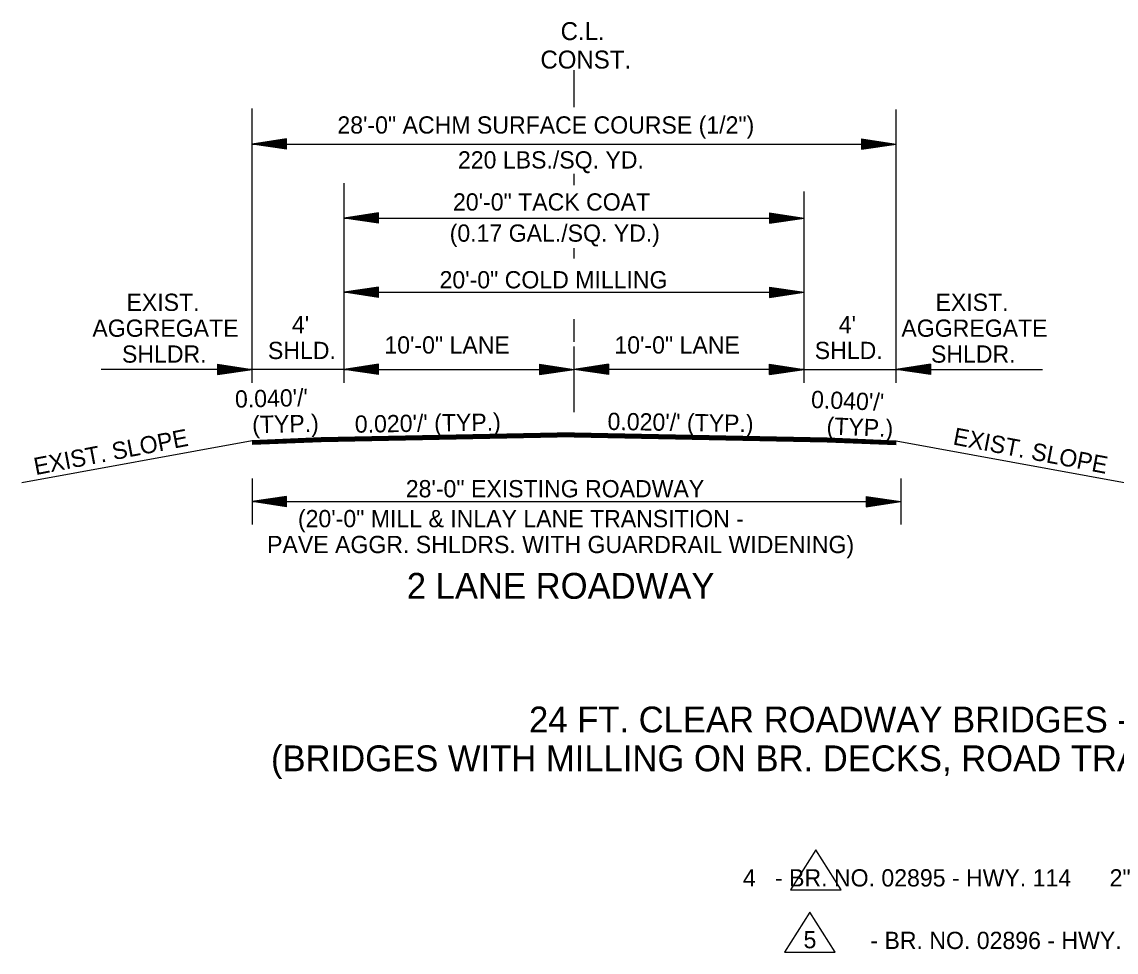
# Model space of a CAD drawing. Extents: x 544259 to 1930787, y -1961343 to 596640.
# Drawn here: x 544331.2 to 544806.9, y -1956857.9 to -1956453.5 of the extents above; entities that cross this region are included whole.
import ezdxf

# ---------------------------------------------------------------- set-up
doc = ezdxf.new("R2010")
doc.units = 0
doc.layers.add('R_Border', color=7, linetype='Continuous')
doc.layers.add('R_Draft', color=7, linetype='Continuous')

msp = doc.modelspace()

# ---------------------------------------------------------------- linework, layer by layer
at = {"layer": 'R_Border'}
for p, q in [((544461.23, -1956634.36), (544431.23, -1956635.56)), ((544461.23, -1956634.66), (544431.23, -1956635.86)), ((544681.23, -1956634.36), (544711.23, -1956635.56)), ((544681.23, -1956634.66), (544711.23, -1956635.86)), ((544461.23, -1956634.96), (544431.23, -1956636.16)), ((544461.23, -1956635.26), (544431.23, -1956636.46)), ((544461.23, -1956635.56), (544431.23, -1956636.76)), ((544461.23, -1956635.86), (544431.23, -1956637.06)), ((544461.23, -1956636.03), (544431.23, -1956637.23)), ((544681.23, -1956634.96), (544711.23, -1956636.16)), ((544681.23, -1956635.26), (544711.23, -1956636.46)), ((544681.23, -1956635.56), (544711.23, -1956636.76)), ((544681.23, -1956635.86), (544711.23, -1956637.06)), ((544681.23, -1956636.03), (544711.23, -1956637.23)), ((544676.31, -1956813.47), (544665.27, -1956830.77)), ((544687.35, -1956830.77), (544676.31, -1956813.47)), ((544665.27, -1956830.77), (544687.35, -1956830.77)), ((544673.76, -1956840.6), (544662.71, -1956857.9)), ((544684.8, -1956857.9), (544673.76, -1956840.6)), ((544662.71, -1956857.9), (544684.8, -1956857.9))]:
    msp.add_line(p, q, dxfattribs=at)
at = {"layer": 'R_Draft'}
for p, q in [((544571.23, -1956490.58), (544571.23, -1956474.51)), ((544431.23, -1956610.43), (544431.23, -1956491.09)), ((544711.23, -1956610.43), (544711.23, -1956491.65)), ((544446.23, -1956504.38), (544431.23, -1956506.63)), ((544446.23, -1956504.76), (544433.73, -1956506.63)), ((544446.23, -1956505.14), (544436.31, -1956506.63)), ((544446.23, -1956505.51), (544438.81, -1956506.63)), ((544446.23, -1956505.9), (544441.35, -1956506.63)), ((544446.23, -1956508.88), (544446.23, -1956504.38)), ((544696.23, -1956504.38), (544711.23, -1956506.63)), ((544696.23, -1956504.38), (544696.23, -1956508.88)), ((544696.23, -1956504.76), (544708.72, -1956506.63)), ((544696.23, -1956505.14), (544706.14, -1956506.63)), ((544696.23, -1956505.51), (544703.65, -1956506.63)), ((544696.23, -1956505.9), (544701.1, -1956506.63)), ((544431.23, -1956506.63), (544711.23, -1956506.63)), ((544446.23, -1956508.88), (544431.23, -1956506.63)), ((544446.23, -1956508.51), (544433.73, -1956506.63)), ((544446.23, -1956508.12), (544436.31, -1956506.63)), ((544446.23, -1956507.75), (544438.81, -1956506.63)), ((544446.23, -1956507.36), (544441.35, -1956506.63)), ((544446.23, -1956506.28), (544443.86, -1956506.63)), ((544446.23, -1956506.98), (544443.86, -1956506.63)), ((544696.23, -1956506.28), (544698.6, -1956506.63)), ((544696.23, -1956508.88), (544711.23, -1956506.63)), ((544696.23, -1956507.37), (544701.1, -1956506.63)), ((544696.23, -1956508.12), (544706.14, -1956506.63)), ((544696.23, -1956508.51), (544708.72, -1956506.63)), ((544696.23, -1956507.75), (544703.65, -1956506.63)), ((544696.23, -1956506.98), (544698.6, -1956506.63)), ((544571.23, -1956524.52), (544571.23, -1956519.49)), ((544471.23, -1956610.43), (544471.23, -1956523.61)), ((544671.23, -1956610.43), (544671.23, -1956527.27)), ((544486.23, -1956536.53), (544471.23, -1956538.78)), ((544471.23, -1956538.78), (544671.23, -1956538.78)), ((544486.23, -1956541.03), (544471.23, -1956538.78)), ((544486.23, -1956536.9), (544473.73, -1956538.78)), ((544486.23, -1956540.65), (544473.73, -1956538.78)), ((544486.23, -1956537.29), (544476.31, -1956538.78)), ((544486.23, -1956540.27), (544476.31, -1956538.78)), ((544486.23, -1956537.66), (544478.81, -1956538.78)), ((544486.23, -1956539.9), (544478.81, -1956538.78)), ((544486.23, -1956538.04), (544481.35, -1956538.78)), ((544486.23, -1956539.51), (544481.35, -1956538.78)), ((544486.23, -1956538.43), (544483.86, -1956538.78)), ((544486.23, -1956539.13), (544483.86, -1956538.78)), ((544486.23, -1956541.03), (544486.23, -1956536.53)), ((544656.23, -1956536.53), (544671.23, -1956538.78)), ((544656.23, -1956536.53), (544656.23, -1956541.03)), ((544656.23, -1956536.9), (544668.72, -1956538.78)), ((544656.23, -1956537.29), (544666.14, -1956538.78)), ((544656.23, -1956537.66), (544663.65, -1956538.78)), ((544656.23, -1956538.05), (544661.1, -1956538.78)), ((544656.23, -1956538.43), (544658.6, -1956538.78)), ((544656.23, -1956541.03), (544671.23, -1956538.78)), ((544656.23, -1956539.51), (544661.1, -1956538.78)), ((544656.23, -1956540.27), (544666.14, -1956538.78)), ((544656.23, -1956540.65), (544668.72, -1956538.78)), ((544656.23, -1956539.9), (544663.65, -1956538.78)), ((544656.23, -1956539.13), (544658.6, -1956538.78)), ((544571.23, -1956556.37), (544571.23, -1956551.91)), ((544486.23, -1956568.77), (544471.23, -1956571.02)), ((544471.23, -1956571.02), (544671.23, -1956571.02)), ((544486.23, -1956573.27), (544471.23, -1956571.02)), ((544486.23, -1956569.14), (544473.73, -1956571.02)), ((544486.23, -1956572.89), (544473.73, -1956571.02)), ((544486.23, -1956569.53), (544476.31, -1956571.02)), ((544486.23, -1956572.51), (544476.31, -1956571.02)), ((544486.23, -1956569.9), (544478.81, -1956571.02)), ((544486.23, -1956572.14), (544478.81, -1956571.02)), ((544486.23, -1956570.28), (544481.35, -1956571.02)), ((544486.23, -1956571.75), (544481.35, -1956571.02)), ((544486.23, -1956570.67), (544483.86, -1956571.02)), ((544486.23, -1956571.37), (544483.86, -1956571.02)), ((544486.23, -1956573.27), (544486.23, -1956568.77)), ((544656.23, -1956568.77), (544671.23, -1956571.02)), ((544656.23, -1956568.77), (544656.23, -1956573.27)), ((544656.23, -1956569.14), (544668.72, -1956571.02)), ((544656.23, -1956569.53), (544666.14, -1956571.02)), ((544656.23, -1956569.9), (544663.65, -1956571.02)), ((544656.23, -1956570.29), (544661.1, -1956571.02)), ((544656.23, -1956570.67), (544658.6, -1956571.02)), ((544656.23, -1956573.27), (544671.23, -1956571.02)), ((544656.23, -1956571.75), (544661.1, -1956571.02)), ((544656.23, -1956572.51), (544666.14, -1956571.02)), ((544656.23, -1956572.89), (544668.72, -1956571.02)), ((544656.23, -1956572.14), (544663.65, -1956571.02)), ((544656.23, -1956571.37), (544658.6, -1956571.02)), ((544571.23, -1956584.55), (544571.23, -1956582.67)), ((544571.23, -1956592.54), (544571.23, -1956584.55)), ((544571.23, -1956623.21), (544571.23, -1956594.66)), ((544471.23, -1956604.56), (544365.65, -1956604.56)), ((544416.23, -1956602.31), (544431.23, -1956604.56)), ((544416.23, -1956602.31), (544416.23, -1956606.81)), ((544416.23, -1956602.68), (544428.72, -1956604.56)), ((544416.23, -1956603.06), (544426.14, -1956604.56)), ((544416.23, -1956603.44), (544423.65, -1956604.56)), ((544416.23, -1956603.83), (544421.1, -1956604.56)), ((544416.23, -1956604.2), (544418.6, -1956604.56)), ((544416.23, -1956606.81), (544431.23, -1956604.56)), ((544416.23, -1956605.29), (544421.1, -1956604.56)), ((544416.23, -1956606.05), (544426.14, -1956604.56)), ((544416.23, -1956606.43), (544428.72, -1956604.56)), ((544416.23, -1956605.67), (544423.65, -1956604.56)), ((544416.23, -1956604.91), (544418.6, -1956604.56)), ((544486.23, -1956602.31), (544471.23, -1956604.56)), ((544486.23, -1956606.81), (544471.23, -1956604.56)), ((544471.23, -1956604.56), (544571.23, -1956604.56)), ((544486.23, -1956602.68), (544473.73, -1956604.56)), ((544486.23, -1956606.43), (544473.73, -1956604.56)), ((544486.23, -1956603.06), (544476.31, -1956604.56)), ((544486.23, -1956606.05), (544476.31, -1956604.56)), ((544486.23, -1956603.44), (544478.81, -1956604.56)), ((544486.23, -1956605.67), (544478.81, -1956604.56)), ((544486.23, -1956603.82), (544481.35, -1956604.56)), ((544486.23, -1956605.28), (544481.35, -1956604.56)), ((544486.23, -1956604.2), (544483.86, -1956604.56)), ((544486.23, -1956604.91), (544483.86, -1956604.56)), ((544486.23, -1956606.81), (544486.23, -1956602.31)), ((544556.23, -1956602.31), (544571.23, -1956604.56)), ((544556.23, -1956602.31), (544556.23, -1956606.81)), ((544556.23, -1956602.68), (544568.72, -1956604.56)), ((544556.23, -1956603.06), (544566.14, -1956604.56)), ((544556.23, -1956603.44), (544563.65, -1956604.56)), ((544556.23, -1956603.83), (544561.1, -1956604.56)), ((544556.23, -1956604.2), (544558.6, -1956604.56)), ((544556.23, -1956606.81), (544571.23, -1956604.56)), ((544556.23, -1956605.29), (544561.1, -1956604.56)), ((544556.23, -1956606.05), (544566.14, -1956604.56)), ((544556.23, -1956606.43), (544568.72, -1956604.56)), ((544556.23, -1956605.67), (544563.65, -1956604.56)), ((544556.23, -1956604.91), (544558.6, -1956604.56)), ((544586.23, -1956602.31), (544571.23, -1956604.56)), ((544671.23, -1956604.56), (544571.23, -1956604.56)), ((544586.23, -1956606.81), (544571.23, -1956604.56)), ((544586.23, -1956602.68), (544573.73, -1956604.56)), ((544586.23, -1956606.43), (544573.73, -1956604.56)), ((544586.23, -1956603.06), (544576.31, -1956604.56)), ((544586.23, -1956606.05), (544576.31, -1956604.56)), ((544586.23, -1956603.44), (544578.81, -1956604.56)), ((544586.23, -1956605.67), (544578.81, -1956604.56)), ((544586.23, -1956603.83), (544581.35, -1956604.56)), ((544586.23, -1956605.29), (544581.35, -1956604.56)), ((544586.23, -1956604.2), (544583.86, -1956604.56)), ((544586.23, -1956604.91), (544583.86, -1956604.56)), ((544586.23, -1956602.31), (544586.23, -1956606.81)), ((544656.23, -1956602.31), (544671.23, -1956604.56)), ((544656.23, -1956606.81), (544656.23, -1956602.31)), ((544656.23, -1956602.68), (544668.72, -1956604.56)), ((544656.23, -1956603.06), (544666.14, -1956604.56)), ((544656.23, -1956603.44), (544663.65, -1956604.56)), ((544656.23, -1956603.82), (544661.1, -1956604.56)), ((544656.23, -1956604.2), (544658.6, -1956604.56)), ((544656.23, -1956606.81), (544671.23, -1956604.56)), ((544656.23, -1956605.28), (544661.1, -1956604.56)), ((544656.23, -1956606.05), (544666.14, -1956604.56)), ((544656.23, -1956606.43), (544668.72, -1956604.56)), ((544656.23, -1956605.67), (544663.65, -1956604.56)), ((544656.23, -1956604.91), (544658.6, -1956604.56)), ((544671.35, -1956604.56), (544774.91, -1956604.56)), ((544726.23, -1956602.31), (544711.23, -1956604.56)), ((544726.23, -1956606.81), (544711.23, -1956604.56)), ((544726.23, -1956602.68), (544713.73, -1956604.56)), ((544726.23, -1956606.43), (544713.73, -1956604.56)), ((544726.23, -1956603.06), (544716.31, -1956604.56)), ((544726.23, -1956606.05), (544716.31, -1956604.56)), ((544726.23, -1956603.44), (544718.81, -1956604.56)), ((544726.23, -1956605.67), (544718.81, -1956604.56)), ((544726.23, -1956603.83), (544721.35, -1956604.56)), ((544726.23, -1956605.29), (544721.35, -1956604.56)), ((544726.23, -1956604.2), (544723.86, -1956604.56)), ((544726.23, -1956604.91), (544723.86, -1956604.56)), ((544726.23, -1956602.31), (544726.23, -1956606.81)), ((544571.23, -1956632.16), (544461.23, -1956634.36)), ((544571.22, -1956632.46), (544461.23, -1956634.66)), ((544571.23, -1956632.76), (544461.23, -1956634.96)), ((544571.25, -1956633.06), (544461.23, -1956635.26)), ((544571.25, -1956633.36), (544461.23, -1956635.56)), ((544571.26, -1956633.66), (544461.23, -1956635.86)), ((544571.26, -1956633.83), (544461.23, -1956636.03)), ((544571.2, -1956633.36), (544681.23, -1956635.56)), ((544571.2, -1956633.66), (544681.23, -1956635.86)), ((544571.2, -1956633.83), (544681.23, -1956636.03)), ((544571.21, -1956633.06), (544681.23, -1956635.26)), ((544571.22, -1956632.46), (544681.23, -1956634.66)), ((544571.22, -1956632.76), (544681.23, -1956634.96)), ((544571.23, -1956632.16), (544681.23, -1956634.36)), ((544431.23, -1956635.56), (544331.16, -1956653.94)), ((544711.23, -1956635.56), (544811.3, -1956653.94)), ((544431.23, -1956652.02), (544431.23, -1956672.02)), ((544713.23, -1956652.02), (544713.23, -1956672.02)), ((544446.23, -1956659.77), (544431.23, -1956662.02)), ((544431.23, -1956662.02), (544711.23, -1956662.02)), ((544446.23, -1956664.27), (544431.23, -1956662.02)), ((544446.23, -1956660.14), (544433.73, -1956662.02)), ((544446.23, -1956663.89), (544433.73, -1956662.02)), ((544446.23, -1956660.53), (544436.31, -1956662.02)), ((544446.23, -1956663.51), (544436.31, -1956662.02)), ((544446.23, -1956660.9), (544438.81, -1956662.02)), ((544446.23, -1956663.14), (544438.81, -1956662.02)), ((544446.23, -1956661.28), (544441.35, -1956662.02)), ((544446.23, -1956662.75), (544441.35, -1956662.02)), ((544446.23, -1956661.67), (544443.86, -1956662.02)), ((544446.23, -1956662.37), (544443.86, -1956662.02)), ((544446.23, -1956664.27), (544446.23, -1956659.77)), ((544698.23, -1956659.77), (544713.23, -1956662.02)), ((544698.23, -1956659.77), (544698.23, -1956664.27)), ((544698.23, -1956660.14), (544710.72, -1956662.02)), ((544698.23, -1956660.53), (544708.14, -1956662.02)), ((544698.23, -1956660.9), (544705.65, -1956662.02)), ((544698.23, -1956661.29), (544703.1, -1956662.02)), ((544698.23, -1956661.67), (544700.6, -1956662.02)), ((544698.23, -1956664.27), (544713.23, -1956662.02)), ((544698.23, -1956662.75), (544703.1, -1956662.02)), ((544698.23, -1956663.51), (544708.14, -1956662.02)), ((544698.23, -1956663.89), (544710.72, -1956662.02)), ((544698.23, -1956663.14), (544705.65, -1956662.02)), ((544698.23, -1956662.37), (544700.6, -1956662.02))]:
    msp.add_line(p, q, dxfattribs=at)

# ---------------------------------------------------------------- texts
for s, height, p in [('C.L.', 7.8, (544565.38, -1956461.42)), ('CONST.', 7.8, (544556.6, -1956473.78)), ('28\'-0" ACHM SURFACE COURSE (1/2")', 7.5, (544468.33, -1956502.06)), ('220 LBS./SQ. YD. ', 7.5, (544520.74, -1956517.24)), ('20\'-0" TACK COAT', 7.5, (544518.58, -1956535.53)), ('(0.17 GAL./SQ. YD.)', 7.5, (544517.14, -1956549.07)), ('20\'-0" COLD MILLING', 7.5, (544512.73, -1956569.35)), ('EXIST.', 7.5, (544376.63, -1956579.15)), ('EXIST.', 7.5, (544728.34, -1956579.15)), ("4' ", 7.5, (544448.57, -1956588.83)), ("4' ", 7.5, (544686.3, -1956588.83)), ('AGGREGATE', 7.5, (544361.81, -1956590.4)), ('AGGREGATE', 7.5, (544713.51, -1956590.4)), ('10\'-0" LANE', 7.5, (544488.75, -1956597.69)), ('10\'-0" LANE', 7.5, (544588.75, -1956597.69)), ('SHLDR.', 7.5, (544374.68, -1956601.65)), ('SHLD.', 7.5, (544438.12, -1956600.08)), ('SHLD.', 7.5, (544675.85, -1956600.08)), ('SHLDR.', 7.5, (544726.39, -1956601.65)), ('28\'-0" EXISTING ROADWAY', 7.5, (544498.06, -1956660.19)), ('(20\'-0" MILL & INLAY LANE TRANSITION -', 7.5, (544451.17, -1956673.19)), ('PAVE AGGR. SHLDRS. WITH GUARDRAIL WIDENING)', 7.5, (544437.76, -1956684.44)), ('2 LANE ROADWAY', 11.25, (544498.5, -1956704.3)), ('24 FT. CLEAR ROADWAY BRIDGES - HYDRODEMOLITION', 11.25, (544551.65, -1956762.41)), ('(BRIDGES WITH MILLING ON BR. DECKS, ROAD TRANSITIONS, AND NEW GUARDRAIL)', 11.25, (544439.46, -1956779.28)), ('      4   - BR. NO. 02895 - HWY. 114      2"', 7.5, (544627.92, -1956829.37)), ('5', 7.5, (544670.98, -1956856.23)), ('- BR. NO. 02896 - HWY. 114      2"', 7.5, (544700.04, -1956856.55))]:
    msp.add_text(s, height=height, dxfattribs=at).set_placement(p)
for s, rotation, p in [("0.040'/' ", 1.3184, (544423.88, -1956621.23)), ("0.040'/' ", 357.6456, (544674.14, -1956621.3)), ('(TYP.)', 1.3184, (544431.35, -1956632.31)), ("0.020'/' (TYP.)", 0.8719, (544475.95, -1956632.12)), ("0.020'/' (TYP.)", 359.1281, (544585.73, -1956630.89)), ('(TYP.)', 357.6456, (544680.87, -1956632.84)), ('EXIST. SLOPE', 10.8829, (544337.14, -1956650.56)), ('EXIST. SLOPE', 349.1171, (544735.61, -1956637.16))]:
    msp.add_text(s, height=7.5, rotation=rotation, dxfattribs=at).set_placement(p)

doc.saveas('drawing.dxf')
